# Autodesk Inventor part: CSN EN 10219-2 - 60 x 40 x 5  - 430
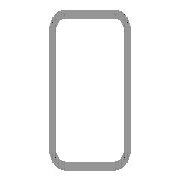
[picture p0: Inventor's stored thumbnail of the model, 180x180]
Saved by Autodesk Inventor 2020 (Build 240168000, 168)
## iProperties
Created: 2019-01
Part Number: CSN EN 10219-2 - 60 x 40 x 5  - 430
Material: Ocel, měkká
Description: Duté svařované profily tvářené za studena z nelegované a jemnozrnné konstrukční oceli
Document SubType Name: Modeling
Standard: CSN EN 10219-2
Designer: doma
Standards Organization: CSN
Language: cs-CZ
Size Designation: 60 x 40 x 5  - 430
Categories: <MemberInstance><Categories><Category DisplayName="Konstrukční profily" InternalName="089c4875-fa83-4c05-b084-43b9cc11f5ed" Mnemonic="GRDR"><CategoryParameter D
Stock Number: 60 x 40 x 5
Density: 7.85 g/cm^3
Appearance: Pololeštěná
Mass: 2820.63 g
Surface Area: 1453.98 cm^2
Volume: 359.316 cm^3
G_L: 430,000 mm
IsCustomPart: 1
Author: doma
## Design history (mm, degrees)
node "Počáteční rovina"
node "Koncová rovina"
sketch "Náčrt"
  geometry: L1 (-20, -20)-(-20, 20); L2 (-10, 30)-(10, 30); L3 (20, 20)-(20, -20); L4 (10, -30)-(-10, -30); L5 (-10, 25)-(10, 25); L6 (15, 20)-(15, -20); L7 (10, -25)-(-10, -25); L8 (-15, -20)-(-15, 20); L9 (0, 37.102)-(0, -37.102) reference; L10 (-23.102, 0)-(23.102, 0) reference; A1 r 10 centre (-10, -20) between (-20, -20) and (-10, -30); A2 r 10 centre (-10, 20) between (-10, 30) and (-20, 20); A3 r 10 centre (10, 20) between (20, 20) and (10, 30); A4 r 10 centre (10, -20) between (10, -30) and (20, -20); A5 r 5 centre (-10, 20) between (-10, 25) and (-15, 20); A6 r 5 centre (10, 20) between (15, 20) and (10, 25); A7 r 5 centre (10, -20) between (10, -25) and (15, -20); A8 r 5 centre (-10, -20) between (-15, -20) and (-10, -25)
  constraints: 16 end point, 16 point on circle, 8 centre point, 8 tangent, 4 parallel, 3 equal radius, 2 perpendicular, 7 other
  dimensions: "d7" = 10 radius of A1 (= G_IR); "d10" = 60 distance between parallel lines of L2 L4 (= G_H); "d11" = 40 distance between parallel lines of L1 L3 (= G_W); "d12" = 5 distance between parallel lines of L3 L6 (= G_T); "d15" = 30 distance between parallel lines of L2 L10 (= 0.5 x d10); "d16" = 20 distance between parallel lines of L9 L3 (= 0.5 x d11)
extrude "Těleso" new body sketch "Náčrt" stored distance "d3" = 430 (= G_L); taper "d4" = 0 deg
node "Driven Length"
  sketch "Sketch3"
    geometry: L1 (0, 0)-(10, 0) reference
    constraints: 2 end point, 1 horizontal
  workplane "Work Plane3"
  sketch "Sketch4"
    geometry: L1 (-2, 0)-(12, 0) reference; L2 (-2, 430)-(12, 430) reference
    dimensions: "d18" = 430 distance between parallel lines of L1 L2 (derived)
body "Solid1"
other parameters: "G_W" = 40 [user parameter; used in 1 equation term], "G_H" = 60 [user parameter; used in 1 equation term], "G_T" = 5 [user parameter; used in 1 equation term], "G_IR" = 10 [user parameter; used in 1 equation term], "G_L" = 430 (= d18) [user parameter; used in 1 equation term], "G_OFFSET_START" = 0 [user parameter; used in 1 equation term], "G_OFFSET_END" = 0 [user parameter; used in 1 equation term], "d13" = 0 (computed from G_OFFSET_START), "d17" = 90 deg
